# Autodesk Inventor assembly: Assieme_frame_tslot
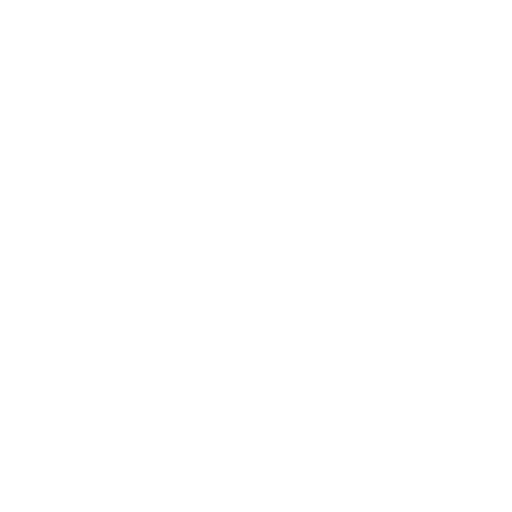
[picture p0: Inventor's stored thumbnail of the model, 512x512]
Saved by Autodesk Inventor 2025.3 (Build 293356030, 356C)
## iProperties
Created: 2026-03
Part Number: Assieme_frame_tslot
Document SubType Name: Assembly
Designer: R5800u
Author: R5800u
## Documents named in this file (1)
- C:\Users\R5800u\Desktop\robot_riduttore_cicloidale2\Assieme_frame_tslot.iam
